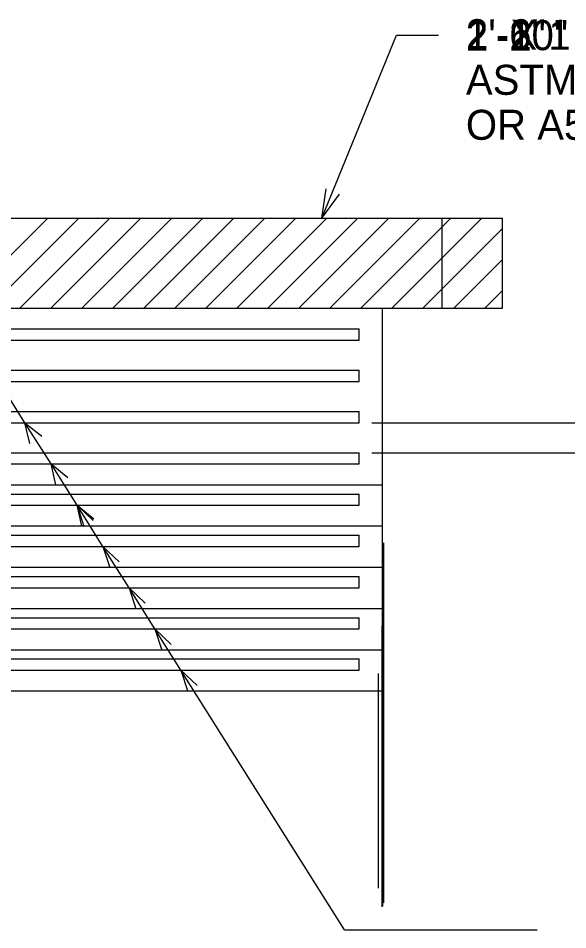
# Model space of a CAD drawing. Extents: x 997.7 to 1009.7, y 1494.3 to 1503.3.
# Drawn here: x 1001.7 to 1002.464, y 1496.988 to 1498.254 of the extents above; entities that cross this region are included whole.
import ezdxf

# ---------------------------------------------------------------- set-up
doc = ezdxf.new("R2010")
doc.units = 0
for name, color, linetype in [('Level 10', 7, 'Continuous'), ('Level 11', 7, 'Continuous'), ('Level 12', 7, 'Continuous'), ('Level 13', 7, 'Continuous'), ('Level 14', 7, 'Continuous'), ('Level 15', 7, 'Continuous'), ('Level 2', 7, 'Continuous'), ('Level 4', 7, 'Continuous'), ('Level 5', 7, 'Continuous'), ('Level 6', 7, 'Continuous'), ('Level 7', 7, 'Continuous'), ('Level 8', 7, 'Continuous'), ('Level 9', 7, 'Continuous')]:
    doc.layers.add(name, color=color, linetype=linetype)

msp = doc.modelspace()

# ---------------------------------------------------------------- linework, layer by layer
at = {"layer": 'Level 10'}
for p, q in [((1002.2058, 1497.6791), (1002.2058, 1497.5488)), ((1000.9044, 1497.5932), (1002.1738, 1497.5932)), ((1002.1738, 1497.5776), (1002.1738, 1497.5932)), ((1000.9044, 1497.5776), (1002.1738, 1497.5776)), ((1000.8725, 1497.5488), (1002.2058, 1497.5488)), ((1002.2074, 1497.5252), (1002.2074, 1497.0253))]:
    msp.add_line(p, q, dxfattribs=at)
msp.add_lwpolyline([(1001.7886, 1497.5486), (1001.7818, 1497.5776), (1001.8051, 1497.5589)], dxfattribs=at)
at = {"layer": 'Level 11'}
for p, q in [((1002.2058, 1497.6791), (1002.2058, 1497.4915)), ((1000.9044, 1497.5932), (1002.1738, 1497.5932)), ((1002.1738, 1497.5776), (1002.1738, 1497.5932)), ((1000.9044, 1497.5776), (1002.1738, 1497.5776)), ((1001.7818, 1497.5776), (1001.8041, 1497.5562)), ((1001.7818, 1497.5776), (1001.7915, 1497.5482)), ((1000.9044, 1497.5359), (1002.1738, 1497.5359)), ((1002.1738, 1497.5203), (1002.1738, 1497.5359)), ((1000.9044, 1497.5203), (1002.1738, 1497.5203)), ((1001.8179, 1497.5203), (1001.8403, 1497.4989)), ((1001.8179, 1497.5203), (1001.8276, 1497.4909)), ((1000.8725, 1497.4915), (1002.2058, 1497.4915)), ((1002.2058, 1497.4606), (1002.2058, 1497.0205))]:
    msp.add_line(p, q, dxfattribs=at)
at = {"layer": 'Level 12'}
for p, q in [((1002.2058, 1497.6783), (1002.2058, 1497.4342)), ((1000.9044, 1497.5932), (1002.1738, 1497.5932)), ((1002.1738, 1497.5776), (1002.1738, 1497.5932)), ((1000.9044, 1497.5776), (1002.1738, 1497.5776)), ((1001.7818, 1497.5776), (1001.8041, 1497.5562)), ((1001.7818, 1497.5776), (1001.7915, 1497.5482)), ((1000.9044, 1497.5359), (1002.1738, 1497.5359)), ((1002.1738, 1497.5203), (1002.1738, 1497.5359)), ((1000.9044, 1497.5203), (1002.1738, 1497.5203)), ((1001.8179, 1497.5203), (1001.8403, 1497.4989)), ((1001.8179, 1497.5203), (1001.8276, 1497.4909)), ((1000.9044, 1497.4787), (1002.1738, 1497.4787)), ((1002.1738, 1497.463), (1002.1738, 1497.4787)), ((1000.9044, 1497.463), (1002.1738, 1497.463)), ((1001.8541, 1497.463), (1001.8764, 1497.4416)), ((1001.8541, 1497.463), (1001.8637, 1497.4336)), ((1000.8725, 1497.4342), (1002.2058, 1497.4342)), ((1002.2052, 1497.41), (1002.2052, 1497.0198))]:
    msp.add_line(p, q, dxfattribs=at)
at = {"layer": 'Level 13'}
for p, q in [((1002.2058, 1497.6791), (1002.2058, 1497.3769)), ((1000.9044, 1497.5932), (1002.1738, 1497.5932)), ((1002.1738, 1497.5776), (1002.1738, 1497.5932)), ((1000.9044, 1497.5776), (1002.1738, 1497.5776)), ((1001.7818, 1497.5776), (1001.8041, 1497.5562)), ((1001.7818, 1497.5776), (1001.7915, 1497.5482)), ((1000.9044, 1497.5359), (1002.1738, 1497.5359)), ((1002.1738, 1497.5203), (1002.1738, 1497.5359)), ((1000.9044, 1497.5203), (1002.1738, 1497.5203)), ((1001.8179, 1497.5203), (1001.8403, 1497.4989)), ((1001.8179, 1497.5203), (1001.8276, 1497.4909)), ((1000.9044, 1497.4787), (1002.1738, 1497.4787)), ((1002.1738, 1497.463), (1002.1738, 1497.4787)), ((1000.9044, 1497.463), (1002.1738, 1497.463)), ((1001.8541, 1497.463), (1001.8764, 1497.4416)), ((1001.8541, 1497.463), (1001.8637, 1497.4336)), ((1000.9044, 1497.4214), (1002.1738, 1497.4214)), ((1002.1738, 1497.4057), (1002.1738, 1497.4214)), ((1000.9044, 1497.4057), (1002.1738, 1497.4057)), ((1001.8901, 1497.4057), (1001.9125, 1497.3843)), ((1001.8901, 1497.4057), (1001.8998, 1497.3763)), ((1000.8725, 1497.3769), (1002.2058, 1497.3769)), ((1002.2002, 1497.3438), (1002.2002, 1497.0458))]:
    msp.add_line(p, q, dxfattribs=at)
at = {"layer": 'Level 14'}
for p, q in [((1002.2058, 1497.6791), (1002.2058, 1497.3196)), ((1000.9044, 1497.5932), (1002.1738, 1497.5932)), ((1002.1738, 1497.5776), (1002.1738, 1497.5932)), ((1000.9044, 1497.5776), (1002.1738, 1497.5776)), ((1001.7818, 1497.5776), (1001.8041, 1497.5562)), ((1001.7818, 1497.5776), (1001.7915, 1497.5482)), ((1000.9044, 1497.5359), (1002.1738, 1497.5359)), ((1002.1738, 1497.5203), (1002.1738, 1497.5359)), ((1000.9044, 1497.5203), (1002.1738, 1497.5203)), ((1001.8179, 1497.5203), (1001.8403, 1497.4989)), ((1001.8179, 1497.5203), (1001.8276, 1497.4909)), ((1000.9044, 1497.4787), (1002.1738, 1497.4787)), ((1002.1738, 1497.463), (1002.1738, 1497.4787)), ((1000.9044, 1497.463), (1002.1738, 1497.463)), ((1001.8541, 1497.463), (1001.8764, 1497.4416)), ((1001.8541, 1497.463), (1001.8637, 1497.4336)), ((1000.9044, 1497.4214), (1002.1738, 1497.4214)), ((1002.1738, 1497.4057), (1002.1738, 1497.4214)), ((1000.9044, 1497.4057), (1002.1738, 1497.4057)), ((1001.8901, 1497.4057), (1001.9125, 1497.3843)), ((1001.8901, 1497.4057), (1001.8998, 1497.3763)), ((1000.9044, 1497.3641), (1002.1738, 1497.3641)), ((1002.1738, 1497.3484), (1002.1738, 1497.3641)), ((1000.9044, 1497.3484), (1002.1738, 1497.3484)), ((1001.9262, 1497.3484), (1001.9486, 1497.327)), ((1001.9262, 1497.3484), (1001.9359, 1497.319)), ((1000.8725, 1497.3196), (1002.2058, 1497.3196)), ((1002.2061, 1497.2908), (1002.2061, 1497.0207))]:
    msp.add_line(p, q, dxfattribs=at)
at = {"layer": 'Level 15'}
for p, q in [((1000.7055, 1497.9763), (1002.3728, 1497.9763)), ((1001.6161, 1497.8513), (1001.7411, 1497.9763)), ((1001.6592, 1497.8513), (1001.7842, 1497.9763)), ((1001.7022, 1497.8513), (1001.8272, 1497.9763)), ((1001.7453, 1497.8513), (1001.8703, 1497.9763)), ((1001.7884, 1497.8513), (1001.9134, 1497.9763)), ((1001.8315, 1497.8513), (1001.9565, 1497.9763)), ((1001.8746, 1497.8513), (1001.9996, 1497.9763)), ((1001.9177, 1497.8513), (1002.0427, 1497.9763)), ((1001.9607, 1497.8513), (1002.0857, 1497.9763)), ((1002.0038, 1497.8513), (1002.1288, 1497.9763)), ((1002.0469, 1497.8513), (1002.1719, 1497.9763)), ((1002.09, 1497.8513), (1002.215, 1497.9763)), ((1002.1331, 1497.8513), (1002.2581, 1497.9763)), ((1002.1762, 1497.8513), (1002.3012, 1497.9763)), ((1002.2192, 1497.8513), (1002.3442, 1497.9763)), ((1002.3728, 1497.8513), (1002.3728, 1497.9763)), ((1002.2623, 1497.8513), (1002.3728, 1497.9618)), ((1002.3054, 1497.8513), (1002.3728, 1497.9188)), ((1002.3485, 1497.8513), (1002.3728, 1497.8757)), ((1000.7055, 1497.8513), (1002.3728, 1497.8513))]:
    msp.add_line(p, q, dxfattribs=at)
at = {"layer": 'Level 2'}
for p, q in [((1002.122, 1497.9763), (1002.2259, 1498.2304)), ((1002.2259, 1498.2304), (1002.2838, 1498.2304)), ((1002.122, 1497.9763), (1002.128, 1498.0172)), ((1002.122, 1497.9763), (1002.1465, 1498.0096)), ((1002.2058, 1497.8513), (1002.2058, 1497.6791)), ((1000.9044, 1497.8224), (1002.1738, 1497.8224)), ((1002.1738, 1497.8068), (1002.1738, 1497.8224)), ((1000.9044, 1497.8068), (1002.1738, 1497.8068)), ((1000.9044, 1497.7651), (1002.1738, 1497.7651)), ((1002.1738, 1497.7495), (1002.1738, 1497.7651)), ((1000.9044, 1497.7495), (1002.1738, 1497.7495)), ((1001.7095, 1497.6922), (1001.6734, 1497.7495)), ((1000.9044, 1497.7078), (1002.1738, 1497.7078)), ((1002.1738, 1497.6922), (1002.1738, 1497.7078)), ((1000.9044, 1497.6922), (1002.1738, 1497.6922)), ((1001.7457, 1497.6349), (1001.7095, 1497.6922)), ((1002.1914, 1497.6922), (1002.6603, 1497.6922)), ((1000.9044, 1497.6505), (1002.1738, 1497.6505)), ((1002.1738, 1497.6349), (1002.1738, 1497.6505)), ((1002.1914, 1497.6505), (1002.6603, 1497.6505)), ((1000.9044, 1497.6349), (1002.1738, 1497.6349)), ((1001.7818, 1497.5776), (1001.7457, 1497.6349)), ((1001.8179, 1497.5203), (1001.7818, 1497.5776)), ((1001.8541, 1497.463), (1001.8179, 1497.5203)), ((1001.8901, 1497.4057), (1001.8541, 1497.463)), ((1001.9262, 1497.3484), (1001.8901, 1497.4057)), ((1002.1533, 1496.9879), (1001.9262, 1497.3484)), ((1002.1533, 1496.9879), (1002.4212, 1496.9879))]:
    msp.add_line(p, q, dxfattribs=at)
for points in [[(1001.7164, 1497.6632), (1001.7095, 1497.6922), (1001.7328, 1497.6735)], [(1001.7525, 1497.6059), (1001.7457, 1497.6349), (1001.7689, 1497.6162)]]:
    msp.add_lwpolyline(points, dxfattribs=at)
at = {"layer": 'Level 4'}
for p, q in [((1000.7892, 1497.9763), (1002.2892, 1497.9763)), ((1001.6161, 1497.8513), (1001.7411, 1497.9763)), ((1001.6592, 1497.8513), (1001.7842, 1497.9763)), ((1001.7022, 1497.8513), (1001.8272, 1497.9763)), ((1001.7453, 1497.8513), (1001.8703, 1497.9763)), ((1001.7884, 1497.8513), (1001.9134, 1497.9763)), ((1001.8315, 1497.8513), (1001.9565, 1497.9763)), ((1001.8746, 1497.8513), (1001.9996, 1497.9763)), ((1001.9177, 1497.8513), (1002.0427, 1497.9763)), ((1001.9607, 1497.8513), (1002.0857, 1497.9763)), ((1002.0038, 1497.8513), (1002.1288, 1497.9763)), ((1002.0469, 1497.8513), (1002.1719, 1497.9763)), ((1002.09, 1497.8513), (1002.215, 1497.9763)), ((1002.1331, 1497.8513), (1002.2581, 1497.9763)), ((1002.2892, 1497.8513), (1002.2892, 1497.9763)), ((1002.1762, 1497.8513), (1002.2892, 1497.9643)), ((1002.2192, 1497.8513), (1002.2892, 1497.9213)), ((1002.2623, 1497.8513), (1002.2892, 1497.8782)), ((1000.7892, 1497.8513), (1002.2892, 1497.8513))]:
    msp.add_line(p, q, dxfattribs=at)
at = {"layer": 'Level 5'}
for p, q in [((1000.7892, 1497.9763), (1002.2892, 1497.9763)), ((1001.6161, 1497.8513), (1001.7411, 1497.9763)), ((1001.6592, 1497.8513), (1001.7842, 1497.9763)), ((1001.7022, 1497.8513), (1001.8272, 1497.9763)), ((1001.7453, 1497.8513), (1001.8703, 1497.9763)), ((1001.7884, 1497.8513), (1001.9134, 1497.9763)), ((1001.8315, 1497.8513), (1001.9565, 1497.9763)), ((1001.8746, 1497.8513), (1001.9996, 1497.9763)), ((1001.9177, 1497.8513), (1002.0427, 1497.9763)), ((1001.9607, 1497.8513), (1002.0857, 1497.9763)), ((1002.0038, 1497.8513), (1002.1288, 1497.9763)), ((1002.0469, 1497.8513), (1002.1719, 1497.9763)), ((1002.09, 1497.8513), (1002.215, 1497.9763)), ((1002.1331, 1497.8513), (1002.2581, 1497.9763)), ((1002.2892, 1497.8513), (1002.2892, 1497.9763)), ((1002.1762, 1497.8513), (1002.2892, 1497.9643)), ((1002.2192, 1497.8513), (1002.2892, 1497.9213)), ((1002.2623, 1497.8513), (1002.2892, 1497.8782)), ((1000.7892, 1497.8513), (1002.2892, 1497.8513))]:
    msp.add_line(p, q, dxfattribs=at)
at = {"layer": 'Level 6'}
for p, q in [((1000.7892, 1497.9763), (1002.2892, 1497.9763)), ((1001.6161, 1497.8513), (1001.7411, 1497.9763)), ((1001.6592, 1497.8513), (1001.7842, 1497.9763)), ((1001.7022, 1497.8513), (1001.8272, 1497.9763)), ((1001.7453, 1497.8513), (1001.8703, 1497.9763)), ((1001.7884, 1497.8513), (1001.9134, 1497.9763)), ((1001.8315, 1497.8513), (1001.9565, 1497.9763)), ((1001.8746, 1497.8513), (1001.9996, 1497.9763)), ((1001.9177, 1497.8513), (1002.0427, 1497.9763)), ((1001.9607, 1497.8513), (1002.0857, 1497.9763)), ((1002.0038, 1497.8513), (1002.1288, 1497.9763)), ((1002.0469, 1497.8513), (1002.1719, 1497.9763)), ((1002.09, 1497.8513), (1002.215, 1497.9763)), ((1002.1331, 1497.8513), (1002.2581, 1497.9763)), ((1002.2892, 1497.8513), (1002.2892, 1497.9763)), ((1002.1762, 1497.8513), (1002.2892, 1497.9643)), ((1002.2192, 1497.8513), (1002.2892, 1497.9213)), ((1002.2623, 1497.8513), (1002.2892, 1497.8782)), ((1000.7892, 1497.8513), (1002.2892, 1497.8513))]:
    msp.add_line(p, q, dxfattribs=at)
at = {"layer": 'Level 7'}
for p, q in [((1000.7892, 1497.9763), (1002.2892, 1497.9763)), ((1001.6161, 1497.8513), (1001.7411, 1497.9763)), ((1001.6592, 1497.8513), (1001.7842, 1497.9763)), ((1001.7022, 1497.8513), (1001.8272, 1497.9763)), ((1001.7453, 1497.8513), (1001.8703, 1497.9763)), ((1001.7884, 1497.8513), (1001.9134, 1497.9763)), ((1001.8315, 1497.8513), (1001.9565, 1497.9763)), ((1001.8746, 1497.8513), (1001.9996, 1497.9763)), ((1001.9177, 1497.8513), (1002.0427, 1497.9763)), ((1001.9607, 1497.8513), (1002.0857, 1497.9763)), ((1002.0038, 1497.8513), (1002.1288, 1497.9763)), ((1002.0469, 1497.8513), (1002.1719, 1497.9763)), ((1002.09, 1497.8513), (1002.215, 1497.9763)), ((1002.1331, 1497.8513), (1002.2581, 1497.9763)), ((1002.2892, 1497.8513), (1002.2892, 1497.9763)), ((1002.1762, 1497.8513), (1002.2892, 1497.9643)), ((1002.2192, 1497.8513), (1002.2892, 1497.9213)), ((1002.2623, 1497.8513), (1002.2892, 1497.8782)), ((1000.7892, 1497.8513), (1002.2892, 1497.8513))]:
    msp.add_line(p, q, dxfattribs=at)
at = {"layer": 'Level 8'}
for p, q in [((1000.7892, 1497.9763), (1002.2892, 1497.9763)), ((1001.6161, 1497.8513), (1001.7411, 1497.9763)), ((1001.6592, 1497.8513), (1001.7842, 1497.9763)), ((1001.7022, 1497.8513), (1001.8272, 1497.9763)), ((1001.7453, 1497.8513), (1001.8703, 1497.9763)), ((1001.7884, 1497.8513), (1001.9134, 1497.9763)), ((1001.8315, 1497.8513), (1001.9565, 1497.9763)), ((1001.8746, 1497.8513), (1001.9996, 1497.9763)), ((1001.9177, 1497.8513), (1002.0427, 1497.9763)), ((1001.9607, 1497.8513), (1002.0857, 1497.9763)), ((1002.0038, 1497.8513), (1002.1288, 1497.9763)), ((1002.0469, 1497.8513), (1002.1719, 1497.9763)), ((1002.09, 1497.8513), (1002.215, 1497.9763)), ((1002.1331, 1497.8513), (1002.2581, 1497.9763)), ((1002.2892, 1497.8513), (1002.2892, 1497.9763)), ((1002.1762, 1497.8513), (1002.2892, 1497.9643)), ((1002.2192, 1497.8513), (1002.2892, 1497.9213)), ((1002.2623, 1497.8513), (1002.2892, 1497.8782)), ((1000.7892, 1497.8513), (1002.2892, 1497.8513))]:
    msp.add_line(p, q, dxfattribs=at)
at = {"layer": 'Level 9'}
for p, q in [((1002.2058, 1497.6791), (1002.2058, 1497.6061)), ((1000.8725, 1497.6061), (1002.2058, 1497.6061)), ((1002.2058, 1497.5841), (1002.2058, 1497.0226))]:
    msp.add_line(p, q, dxfattribs=at)

# ---------------------------------------------------------------- texts
at = {"layer": 'Level 15'}
msp.add_text('2\'-6"', height=0.04167, dxfattribs=at).set_placement((1002.3221, 1498.211))
at = {"layer": 'Level 2'}
for s, height, p in [('    X 1 1/2" X     PLATE', 0.041667, (1002.3221, 1498.2102)), ('ASTM A709 GRADE 50W', 0.041667, (1002.3221, 1498.1477)), ('OR A588', 0.04167, (1002.3221, 1498.0852))]:
    msp.add_text(s, height=height, dxfattribs=at).set_placement(p)
at = {"layer": 'Level 4'}
msp.add_text('1\'-6"', height=0.04167, dxfattribs=at).set_placement((1002.3221, 1498.211))
at = {"layer": 'Level 5'}
msp.add_text('1\'-6"', height=0.04167, dxfattribs=at).set_placement((1002.3221, 1498.2102))
at = {"layer": 'Level 6'}
msp.add_text('1\'-10"', height=0.04167, dxfattribs=at).set_placement((1002.3221, 1498.2097))
at = {"layer": 'Level 7'}
msp.add_text('2\'-2"', height=0.04167, dxfattribs=at).set_placement((1002.3221, 1498.2097))
at = {"layer": 'Level 8'}
msp.add_text('2\'-2"', height=0.04167, dxfattribs=at).set_placement((1002.3221, 1498.2089))

doc.saveas('drawing.dxf')
